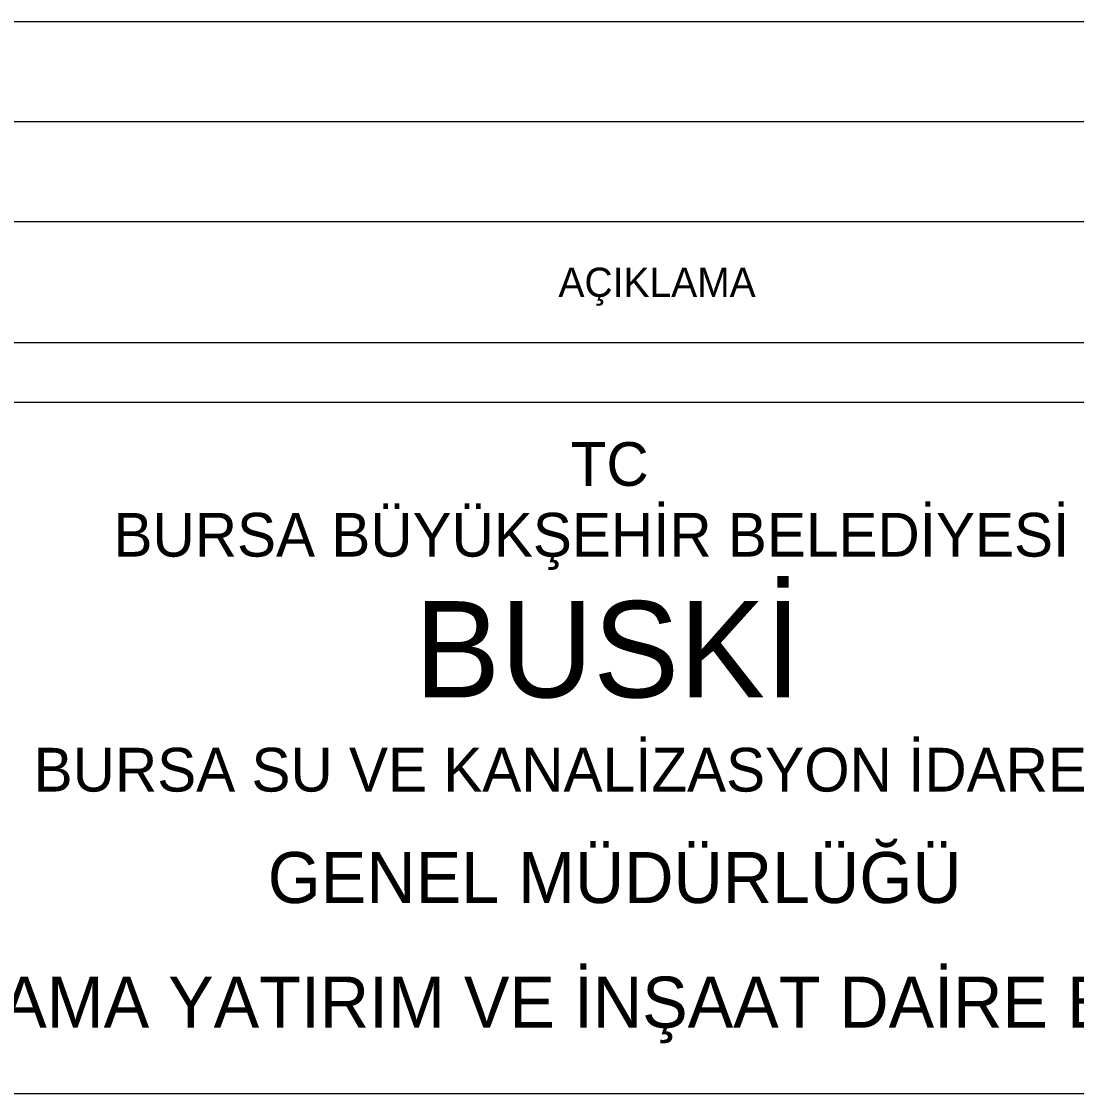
# Model space of a CAD drawing. Extents: x -10 to 1145, y -10 to 821.
# Drawn here: x 1011.5 to 1083.8, y 205.7 to 279.2 of the extents above; entities that cross this region are included whole.
import ezdxf

# ---------------------------------------------------------------- set-up
doc = ezdxf.new("R2010")
doc.units = 0
for name, color, linetype in [('Level 20', 7, 'Continuous'), ('Level 6', 7, 'Continuous'), ('Level 7', 7, 'Continuous')]:
    doc.layers.add(name, color=color, linetype=linetype)

msp = doc.modelspace()

# ---------------------------------------------------------------- linework, layer by layer
at = {"layer": 'Level 6'}
for p, q in [((967.025, 279.244), (1135, 279.244)), ((967.025, 279.244), (1135, 279.244)), ((967.025, 279.244), (1135, 279.244)), ((967.025, 279.244), (1135, 279.244)), ((970.154, 279.244), (1131.871, 279.244)), ((970.154, 279.244), (1131.871, 279.244)), ((970.154, 279.244), (1131.871, 279.244)), ((970.154, 279.244), (1131.871, 279.244)), ((970.154, 279.244), (1131.871, 279.244)), ((970.154, 279.244), (1131.871, 279.244)), ((970.154, 279.244), (1131.871, 279.244)), ((970.154, 279.244), (1131.871, 279.244)), ((967.025, 272.38), (1135, 272.38)), ((967.025, 272.38), (1135, 272.38)), ((967.025, 272.38), (1135, 272.38)), ((967.025, 272.38), (1135, 272.38)), ((967.025, 265.521), (1135, 265.521)), ((967.025, 265.521), (1135, 265.521)), ((967.025, 265.521), (1135, 265.521)), ((967.025, 265.521), (1135, 265.521)), ((967.025, 257.229), (1135, 257.229)), ((967.025, 257.229), (1135, 257.229)), ((967.025, 257.229), (1135, 257.229)), ((967.025, 257.229), (1135, 257.229)), ((967.025, 253.135), (1135, 253.135)), ((967.025, 253.135), (1135, 253.135)), ((967.025, 253.135), (1135, 253.135)), ((967.025, 253.135), (1135, 253.135)), ((967.025, 205.725), (1135, 205.725))]:
    msp.add_line(p, q, dxfattribs=at)

# ---------------------------------------------------------------- texts
at = {"layer": 'Level 20'}
for s, p in [('GENEL MÜDÜRLÜĞÜ', (1028.379, 218.789)), ('PLANLAMA YATIRIM VE İNŞAAT DAİRE BAŞKANLIĞI', (995.276, 210.244))]:
    msp.add_text(s, height=3.5, dxfattribs=at).set_placement(p)
at = {"layer": 'Level 7'}
for s, height, p in [('AÇIKLAMA', 2, (1048.314, 260.358)), ('TC', 3, (1049.153, 247.395)), ('BURSA BÜYÜKŞEHİR BELEDİYESİ', 3, (1017.801, 242.545)), ('BUSKİ', 6.6017, (1038.438, 232.892)), ('BURSA SU VE KANALİZASYON İDARESİ', 3, (1012.326, 226.434))]:
    msp.add_text(s, height=height, dxfattribs=at).set_placement(p)

doc.saveas('drawing.dxf')
